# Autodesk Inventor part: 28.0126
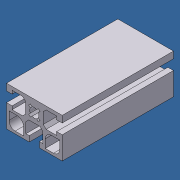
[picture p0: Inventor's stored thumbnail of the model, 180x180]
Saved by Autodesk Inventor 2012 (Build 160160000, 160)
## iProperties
Created: 2007-06
Part Number: 28.0126
Material: Aluminum-6061
Document SubType Name: Modeling
Designer: Andy Moles
Density: 2.71 g/cm^3
Description: L = 3.543"
Stock Number: 20.1055 PROFILE 45X32F
Vendor: F
Mass: 144.784 g
Surface Area: 366.157 cm^2
Volume: 53.4258 cm^3
Author: Andy Moles
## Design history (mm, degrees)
sketch "Sketch1"
  geometry: L1 (-4.596, -3.182)-(-3.263, -1.849) reference; L2 (-3.263, 1.849)-(-4.596, 3.182) reference; L3 (-4.596, 3.182)-(-3.182, 4.596) reference; L4 (-3.182, 4.596)-(-1.849, 3.263) reference; L5 (1.849, 3.263)-(3.182, 4.596) reference; L6 (3.182, 4.596)-(4.596, 3.182) reference; L7 (4.596, 3.182)-(3.263, 1.849) reference; L8 (3.263, -1.849)-(4.596, -3.182) reference; L9 (4.596, -3.182)-(3.182, -4.596) reference; L10 (3.182, -4.596)-(1.849, -3.263) reference; L11 (-1.849, -3.263)-(-3.182, -4.596) reference; L12 (-3.182, -4.596)-(-4.596, -3.182) reference; L13 (13.8, -8.8)-(20.5, -8.8) reference; L14 (20.5, -8.8)-(20.5, -15.5) reference; L15 (15.5, -20.5)-(8.8, -20.5) reference; L16 (8.8, -20.5)-(8.8, -13.8) reference; L17 (-20.5, -8.8)-(-13.8, -8.8) reference; L18 (-8.8, -13.8)-(-8.8, -20.5) reference; L19 (-8.8, -20.5)-(-15.5, -20.5) reference; L20 (-4.1, -22.5)-(-4.1, -18) reference; L21 (-4.6, -18)-(-6.8, -18) reference; L22 (-6.8, -18)-(-6.8, -9.5) reference; L23 (-6.8, -9.5)-(-4.5, -7.2) reference; L24 (-4.5, -7.2)-(4.5, -7.2) reference; L25 (4.5, -7.2)-(6.8, -9.5) reference; L26 (6.8, -9.5)-(6.8, -18) reference; L27 (4.1, -18)-(4.1, -22.5) reference; L28 (22.5, -22.5)-(4.4, -22.5) reference; L29 (22.5, -4.1)-(18, -4.1) reference; L30 (18, -4.1)-(18, -6.8); L31 (18, -6.8)-(9.5, -6.8) reference; L32 (9.5, -6.8)-(7.2, -4.5) reference; L33 (7.2, -4.5)-(7.2, 4.5) reference; L34 (7.2, 4.5)-(9.5, 6.8) reference; L35 (9.5, 6.8)-(18, 6.8) reference; L36 (18, 4.1)-(22.5, 4.1) reference; L37 (-22.5, 9.5)-(22.5, 9.5) reference; L38 (-22.5, 4.1)-(-18, 4.1) reference; L39 (-18, 4.1)-(-18, 6.8); L40 (-18, 6.8)-(-9.5, 6.8) reference; L41 (-9.5, 6.8)-(-7.2, 4.5) reference; L42 (-7.2, 4.5)-(-7.2, -4.5) reference; L43 (-7.2, -4.5)-(-9.5, -6.8) reference; L44 (-9.5, -6.8)-(-18, -6.8) reference; L45 (-18, -4.1)-(-22.5, -4.1) reference; L46 (-22.5, -22.5)-(-22.5, -4.4) reference; L47 (-22.5, -4.4)-(-22.5, -4.1) reference; L48 (-22.5, 4.1)-(-22.5, 9.5) reference; L49 (22.5, 9.5)-(22.5, 4.1) reference; L50 (4.4, -22.5)-(4.1, -22.5) reference; L51 (-4.1, -22.5)-(-22.5, -22.5) reference; L52 (-18, -6.8)-(-18, -4.1) reference; L53 (-20.5, -15.5)-(-20.5, -8.8) reference; L54 (6.8, -18)-(4.1, -18) reference; L55 (-4.1, -18)-(-4.6, -18) reference; L56 (18, 6.8)-(18, 4.1) reference; L57 (22.5, -4.1)-(22.5, -22.5); A1 r 5 centre (13.8, -13.8) between (13.8, -8.8) and (8.8, -13.8) reference; A2 r 5 centre (15.5, -15.5) between (15.5, -20.5) and (20.5, -15.5) reference; A3 r 5 centre (-13.8, -13.8) between (-8.8, -13.8) and (-13.8, -8.8) reference; A4 r 5 centre (-15.5, -15.5) between (-20.5, -15.5) and (-15.5, -20.5) reference; A5 r 3.75 centre (0, 0) between (-3.362, 1.66) and (-3.263, -1.849) reference; A6 r 3.75 centre (0, 0) between (-1.849, -3.263) and (-1.66, -3.362) reference; A7 r 3.75 centre (0, 0) between (1.66, 3.362) and (-1.849, 3.263) reference; A8 r 3.75 centre (0, 0) between (-3.263, 1.849) and (-3.362, 1.66) reference; A9 r 3.75 centre (0, 0) between (3.362, -1.66) and (3.263, 1.849) reference; A10 r 3.75 centre (0, 0) between (1.849, 3.263) and (1.66, 3.362) reference; A11 r 3.75 centre (0, 0) between (-1.66, -3.362) and (1.849, -3.263) reference; A12 r 3.75 centre (0, 0) between (3.263, -1.849) and (3.362, -1.66) reference
  constraints: 114 end point, 24 point on circle, 20 horizontal, 15 vertical, 12 centre point, 1 parallel, 108 other
extrude "Extrusion1" new body sketch "Sketch1" stored distance "d0" = 89.9922; taper "d1" = 0 deg
body "Solid1"
